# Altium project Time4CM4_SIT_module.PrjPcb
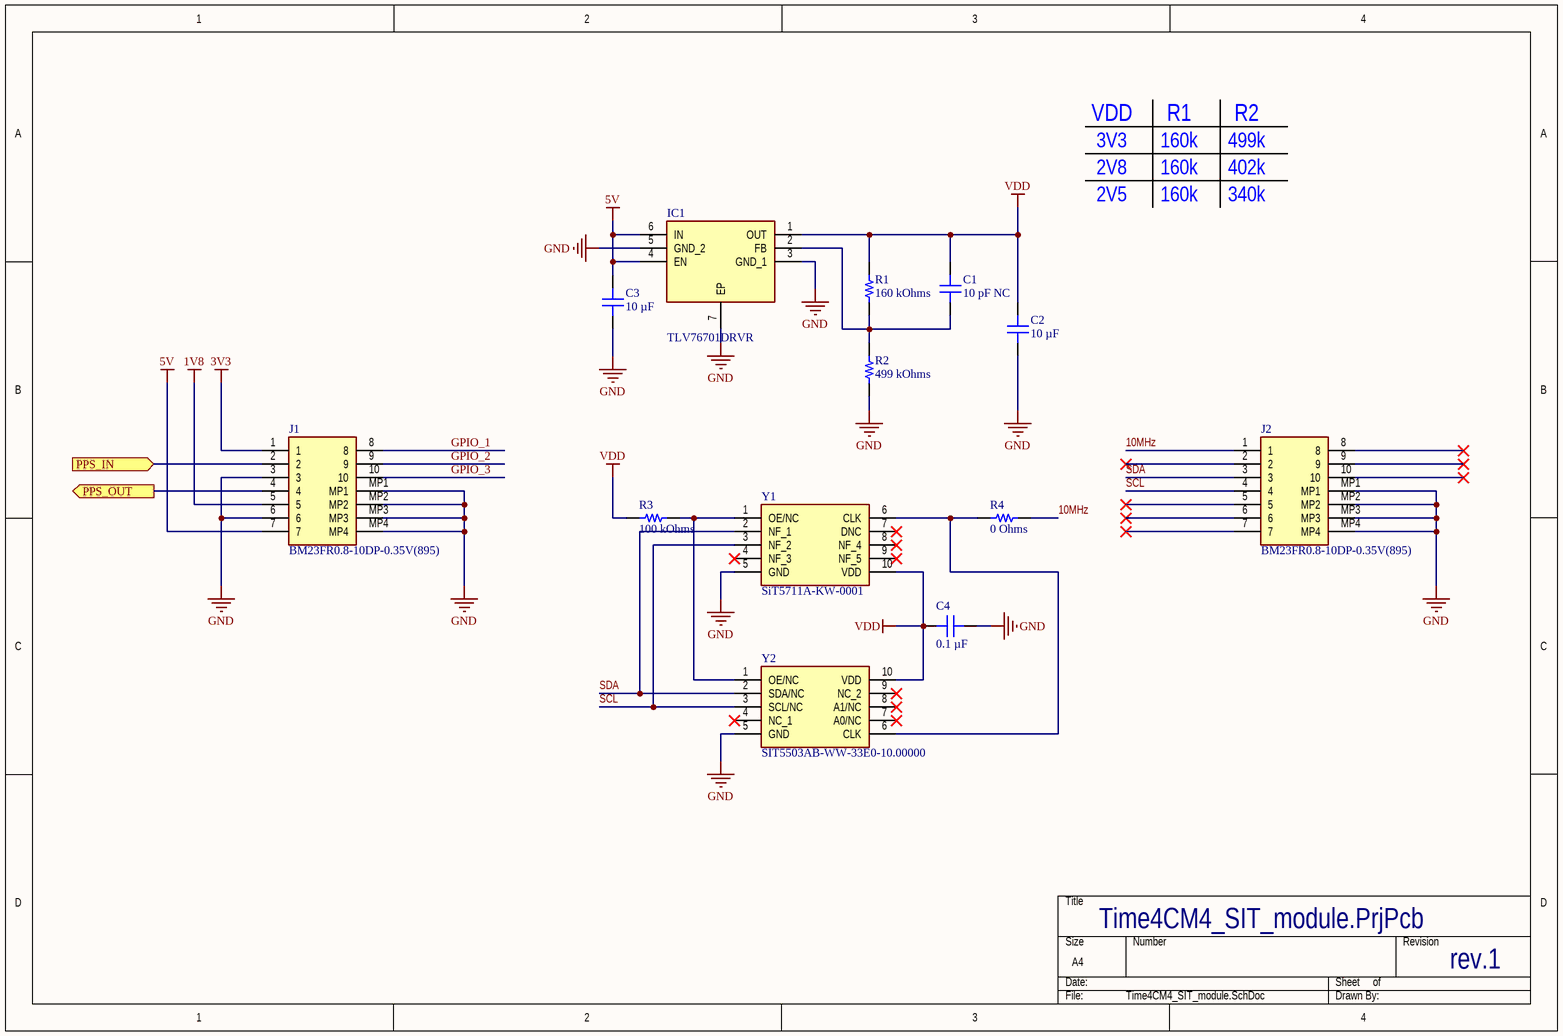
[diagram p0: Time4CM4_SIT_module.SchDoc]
revision: rev.1
1 sheet, 13 parts. Net scope: flat (ports and power ports of the same name join across sheets).
Board file: Time4CM4_SIT_module.PcbDoc

## Sheet Time4CM4_SIT_module.SchDoc
size A4; SheetNumber: 1; SheetTotal: 1

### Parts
C1  10 pF NC  [CAP 0402_1005]
C2  10 µF  [CAP 0603_1608]
C3  10 µF  [CAP 0603_1608]
C4  0.1 µF  [CAP 0402_1005]
IC1  TLV76701DRVR  [SON65P200X200X80-7N]
J1  BM23FR0.8-10DP-0.35V(895)  [BM23FR0810DP035V895]
J2  BM23FR0.8-10DP-0.35V(895)  [BM23FR0810DP035V895]
R1  160 kOhms  [YAGEO RES 0402_1005]
R2  499 kOhms  [YAGEO RES 0402_1005]
R3  100 kOhms  [YAGEO RES 0402_1005]
R4  0 Ohms  [YAGEO RES 0402_1005]
Y1  SiT5711A-KW-0001  [Emerald_9070_10pins_2022]
Y2  SIT5503AB-WW-33E0-10.00000  [Ceramic_QFN_7050_10pins]

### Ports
PPS_IN (in), PPS_OUT (out)

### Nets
1V8: J1.5
3V3: J1.1
5V: C3.2 IC1.4(EN) IC1.6(IN) J1.7
GND: C2.1 C3.1 C4.1 IC1.3(GND_1) IC1.5(GND_2) IC1.7(EP) J1.3 J1.6 J1.MP1 J1.MP2 J1.MP3 J1.MP4 J2.MP1 J2.MP2 J2.MP3 J2.MP4 R2.1 Y1.5(GND) Y2.5(GND)
VDD: C1.2 C2.2 C4.2 IC1.1(OUT) R1.2 R3.1 Y1.10(VDD) Y2.10(VDD)
10MHz: J2.1 R4.1
GPIO_1: J1.8
GPIO_2: J1.9
GPIO_3: J1.10
SCL: J2.4 Y1.3(NF_2) Y2.3(SCL/NC)
SDA: J2.3 Y1.2(NF_1) Y2.2(SDA/NC)
NetC1_1: C1.1 IC1.2(FB) R1.1 R2.2
NetJ1_2: J1.2 ; port PPS_IN
NetJ1_4: J1.4 ; port PPS_OUT
NetR3_2: R3.2 Y1.1(OE/NC) Y2.1(OE/NC)
NetR4_2: R4.2 Y1.6(CLK) Y2.6(CLK)

Not connected (* = marked no-connect by the designer): J2 2* 5* 6* 7* 8* 9* 10*; Y1 4(NF_3)* 7(DNC)* 8(NF_4)* 9(NF_5)*; Y2 4(NC_1)* 7(A0/NC)* 8(A1/NC)* 9(NC_2)*

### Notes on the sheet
- VDD
- R1
- R2
- 2V8
- 3V3
- 160k
- 499k
- 402k
- 2V5
- 340k

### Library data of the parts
C1 = CC0402KRNPO9BN100: CAP CER 10PF 50V C0G/NPO 0402; manufacturer: Yageo; Temperature Coefficient: C0G, NP0; Tolerance: ±10%
C2 C3 = CC0603MPX5R5BB106: CAP CER 10UF 6.3V X5R 0603; manufacturer: Yageo; Tolerance: ±20%
C4 = CC0402KRX7R5BB104: CAP CER 0.1UF 6.3V X7R 0402; manufacturer: Yageo; Tolerance: ±10%
IC1 = TLV76701DRVR: IC REG LINEAR POS ADJ 1A 6WSON; Manufacturer_Name: Texas Instruments
J1 J2 = BM23FR0.8-10DS-0.35V_895_: Connector; Manufacturer_Name: Hirose; Manufacturer_Part_Number: BM23FR0.8-10DS-0.35V(895)
R1 = RC0402FR-07160KL: RES 160K OHM 1% 1/16W 0402; Manufacturer: Yageo; Power (Watts): 0.063W, 1/16W; Temperature Coefficient: ±100ppm/°C
R2 = RC0402FR-07499KL: RES 499K OHM 1% 1/16W 0402; Manufacturer: Yageo; Power (Watts): 0.063W, 1/16W; Temperature Coefficient: ±100ppm/°C
R3 = RC0402FR-07100KL: RES 100K OHM 1% 1/16W 0402; Manufacturer: Yageo; Power (Watts): 0.063W, 1/16W; Temperature Coefficient: ±100ppm/°C
R4 = RC0402FR-070RL: RES 0 OHM JUMPER 1/16W 0402; Manufacturer: Yageo; Power (Watts): 0.063W, 1/16W
Y1 = SiT5711A-KW-0001: Crystal or Oscillator; Manufacturer_Name: SiTime
Y2 = SIT5503AB-WW-33E0-10.00000: Crystal or Oscillator; Manufacturer_Name: SiTime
